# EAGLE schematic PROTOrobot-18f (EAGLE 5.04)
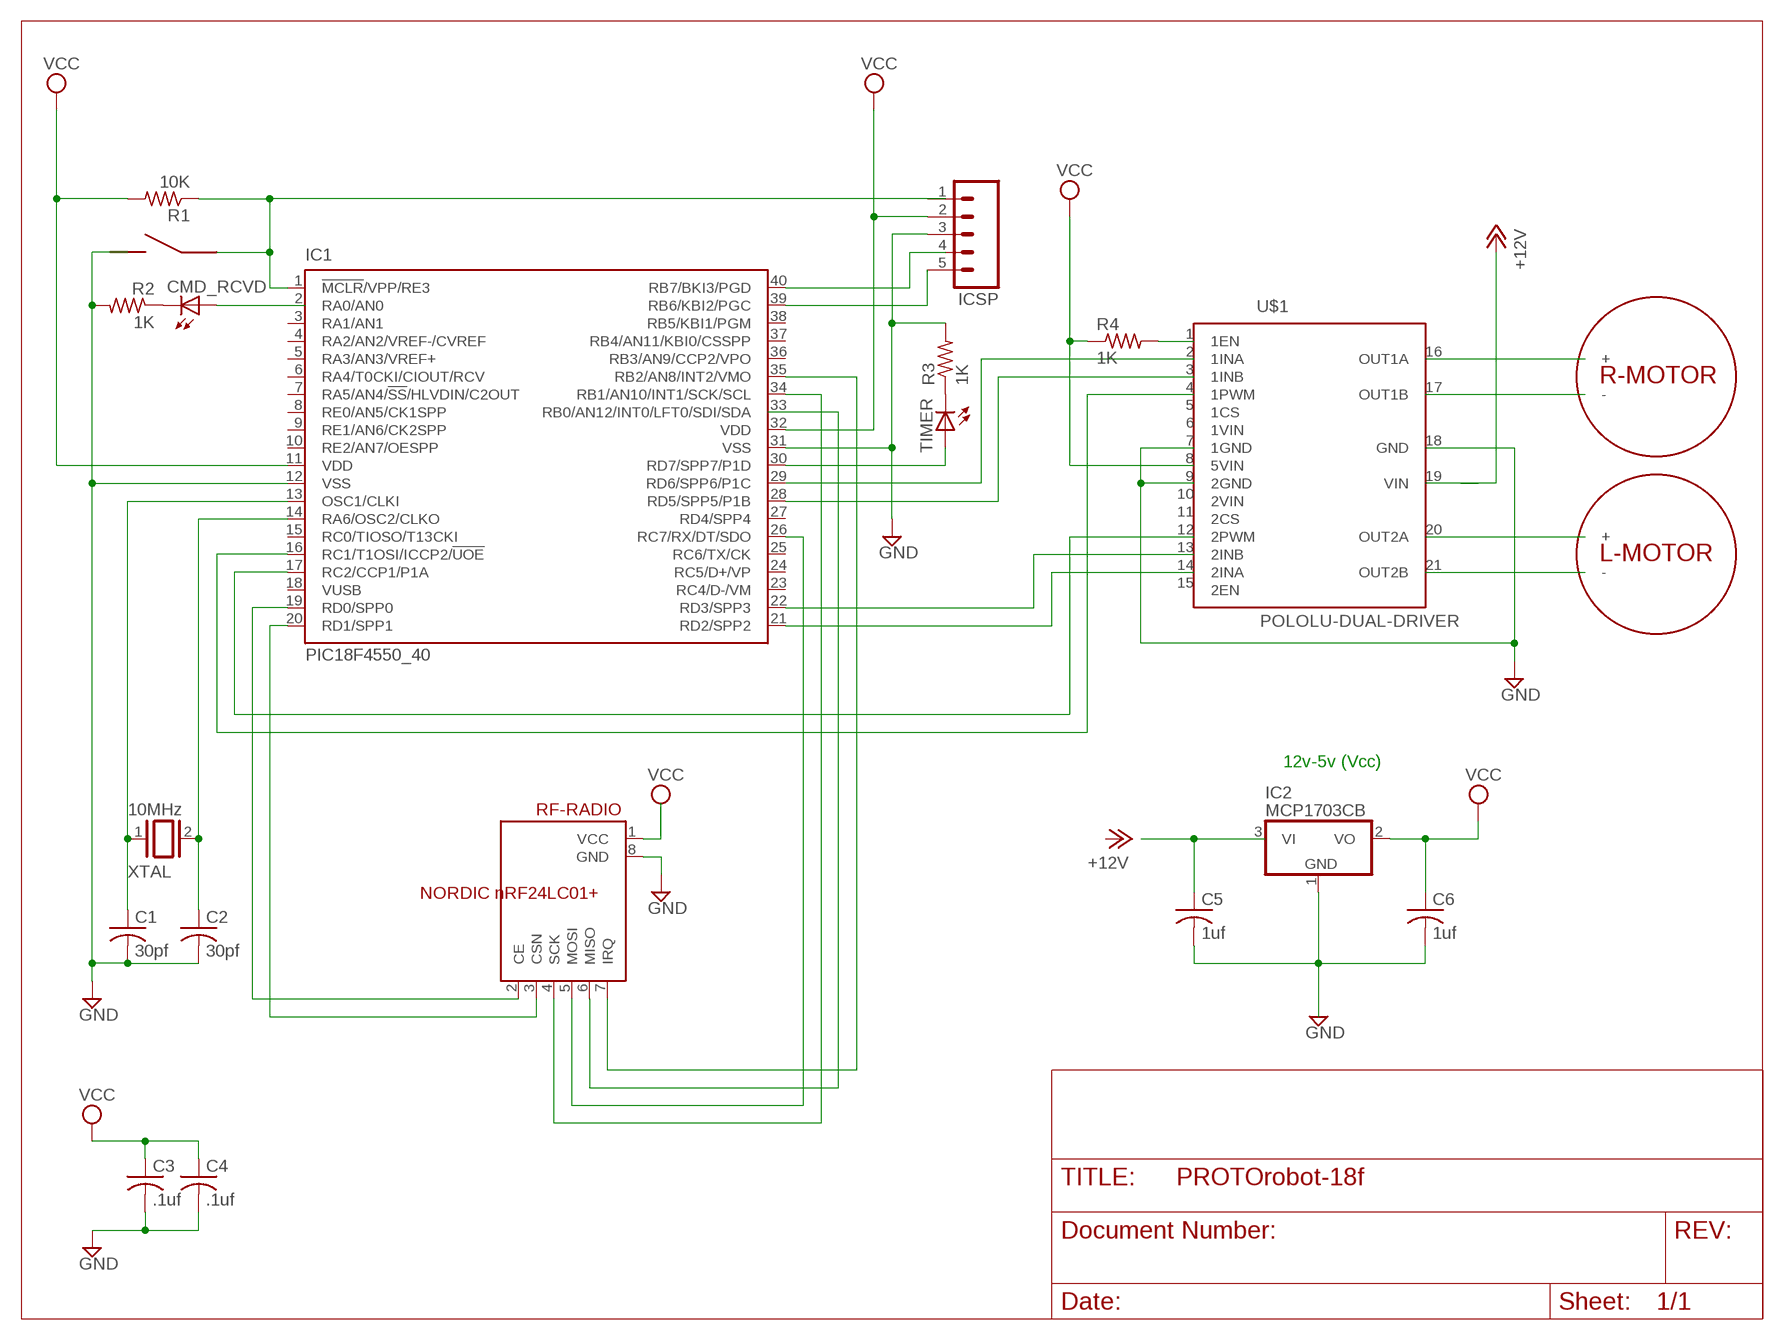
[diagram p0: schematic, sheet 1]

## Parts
C1  30pf  C-US102-043X133  [C102-043X133]
C2  30pf  C-US102-043X133  [C102-043X133]
C3  .1uf  C-US102-043X133  [C102-043X133]
C4  .1uf  C-US102-043X133  [C102-043X133]
C5  1uf  C-US102-043X133  [C102-043X133]
C6  1uf  C-US102-043X133  [C102-043X133]
CMD_RCVD  LEDCHIPLED_0603  [CHIPLED_0603]
IC1  PIC18F4550_40  [DIL40]
IC2  MCP1703CB  [SOT23]
ICSP  M05  [05P]
L-MOTOR  DC-MOTOR  [DC-MOTOR]
R1  10K  R-US_0617/22  [0617/22]
R2  1K  R-US_0617/22  [0617/22]
R3  1K  R-US_0617/22  [0617/22]
R4  1K  R-US_0617/22  [0617/22]
R-MOTOR  DC-MOTOR  [DC-MOTOR]
RESET  PUSH-BUTTON-SWITCH  [2SIL]
RF-RADIO  NORDIC nRF24LC01+  NORDIC-BREAKOUT  [8SIL]
TIMER  LEDCHIPLED_0603  [CHIPLED_0603]
U$1  POLOLU-DUAL-DRIVER  [POLOLU-DUAL-DRIVER]
XTAL  10MHz  XTAL  [Q]

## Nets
+12V: U$1.19(VIN)
GND: C1.2 C2.2 C3.2 C4.2 IC1.12(VSS) IC1.31(VSS) ICSP.3 R2.2 R3.2 RF-RADIO.8(GND) U$1.7(1GND) U$1.9(2GND) U$1.18(GND)
N$1: CMD_RCVD.C R2.1
N$2: CMD_RCVD.A
N$3: R-MOTOR.P$2(-) U$1.17(OUT1B)
N$4: R-MOTOR.P$1(+) U$1.16(OUT1A)
N$5: IC1.39(RB6/KBI2/PGC) ICSP.5
N$6: IC1.40(RB7/BKI3/PGD)
N$8: L-MOTOR.P$1(+) U$1.20(OUT2A)
N$9: C1.1 IC1.13(OSC1/CLKI) XTAL.1
N$10: C2.1 IC1.14(RA6/OSC2/CLKO) XTAL.2
N$11: IC1.19(RD0/SPP0) RF-RADIO.2(CE)
N$12: IC1.16(RC1/T1OSI/ICCP2/!UOE) U$1.4(1PWM)
N$13: U$1.12(2PWM)
N$14: L-MOTOR.P$2(-) U$1.21(OUT2B)
N$15: R4.2 U$1.1(1EN)
N$16: RF-RADIO.6(MISO)
N$17: IC1.20(RD1/SPP1) RF-RADIO.3(CSN)
N$18: R3.1 TIMER.C
N$19: IC1.30(RD7/SPP7/P1D) TIMER.A
N$20: IC1.26(RC7/RX/DT/SDO) RF-RADIO.5(MOSI)
N$21: IC1.34(RB1/AN10/INT1/SCK/SCL) RF-RADIO.4(SCK)
N$22: IC1.35(RB2/AN8/INT2/VMO) RF-RADIO.7(IRQ)
N$23: IC1.21(RD2/SPP2) U$1.14(2INA)
N$25: IC1.22(RD3/SPP3) U$1.13(2INB)
N$26: IC1.28(RD5/SPP5/P1B) U$1.3(1INB)
N$27: IC1.29(RD6/SPP6/P1C) U$1.2(1INA)
N$28: IC1.1(!MCLR!/VPP/RE3) R1.1 RESET.NO
N$29: C5.1
N$30: C5.2 C6.2 IC2.1(GND)
VCC: C3.1 C4.1 C6.1 IC1.11(VDD) IC1.32(VDD) IC2.2(VO) ICSP.2 R1.2 R4.1 RF-RADIO.1(VCC) U$1.8(5VIN)
Unconnected: IC1.2(RA0/AN0) IC1.3(RA1/AN1) IC1.4(RA2/AN2/VREF-/CVREF) IC1.5(RA3/AN3/VREF+) IC1.6(RA4/T0CKI/CIOUT/RCV) IC1.7(RA5/AN4/!SS!/HLVDIN/C2OUT) IC1.8(RE0/AN5/CK1SPP) IC1.9(RE1/AN6/CK2SPP) IC1.10(RE2/AN7/OESPP) IC1.15(RC0/TIOSO/T13CKI) IC1.17(RC2/CCP1/P1A) IC1.18(VUSB) IC1.23(RC4/D-/VM) IC1.24(RC5/D+/VP) IC1.25(RC6/TX/CK) IC1.27(RD4/SPP4) IC1.33(RB0/AN12/INT0/LFT0/SDI/SDA) IC1.36(RB3/AN9/CCP2/VPO) IC1.37(RB4/AN11/KBI0/CSSPP) IC1.38(RB5/KBI1/PGM) IC2.3(VI) ICSP.1 ICSP.4 RESET.COM U$1.5(1CS) U$1.6(1VIN) U$1.10(2VIN) U$1.11(2CS) U$1.15(2EN)

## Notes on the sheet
- 12v-5v (Vcc)

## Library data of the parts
C1-C6 = rcl:C-US: CAPACITOR, American symbol
CMD_RCVD TIMER = led:LED: LED
IC1 = microchip:PIC18F4*_40: USB Microcontrollers with nanoWatt Technology High-Performance, Enhanced Flash, 28/40/44-Pin, Source: http://ww1.microchip.com/downloads/en/devicedoc/39632c.pdf
IC2 = linear:MCP1703: 250 mA, 16V, Low Quiescent Current LDO Regulator Source: http://ww1.microchip.com/downloads/en/DeviceDoc/22049b.pdf
ICSP = con-amp-quick:M05: AMP QUICK CONNECTOR
L-MOTOR R-MOTOR = trl:DC-MOTOR: DC Motor
R1-R4 = resistor:R-US_: RESISTOR, American symbol
RESET = trl:PUSH-BUTTON-SWITCH
RF-RADIO = trl:NORDIC-BREAKOUT: Spark Fun Electronic's Nordic Semiconductor nRF24L01 with chip antenna
U$1 = trl:POLOLU-DUAL-DRIVER
XTAL = special:XTAL: CRYSTAL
